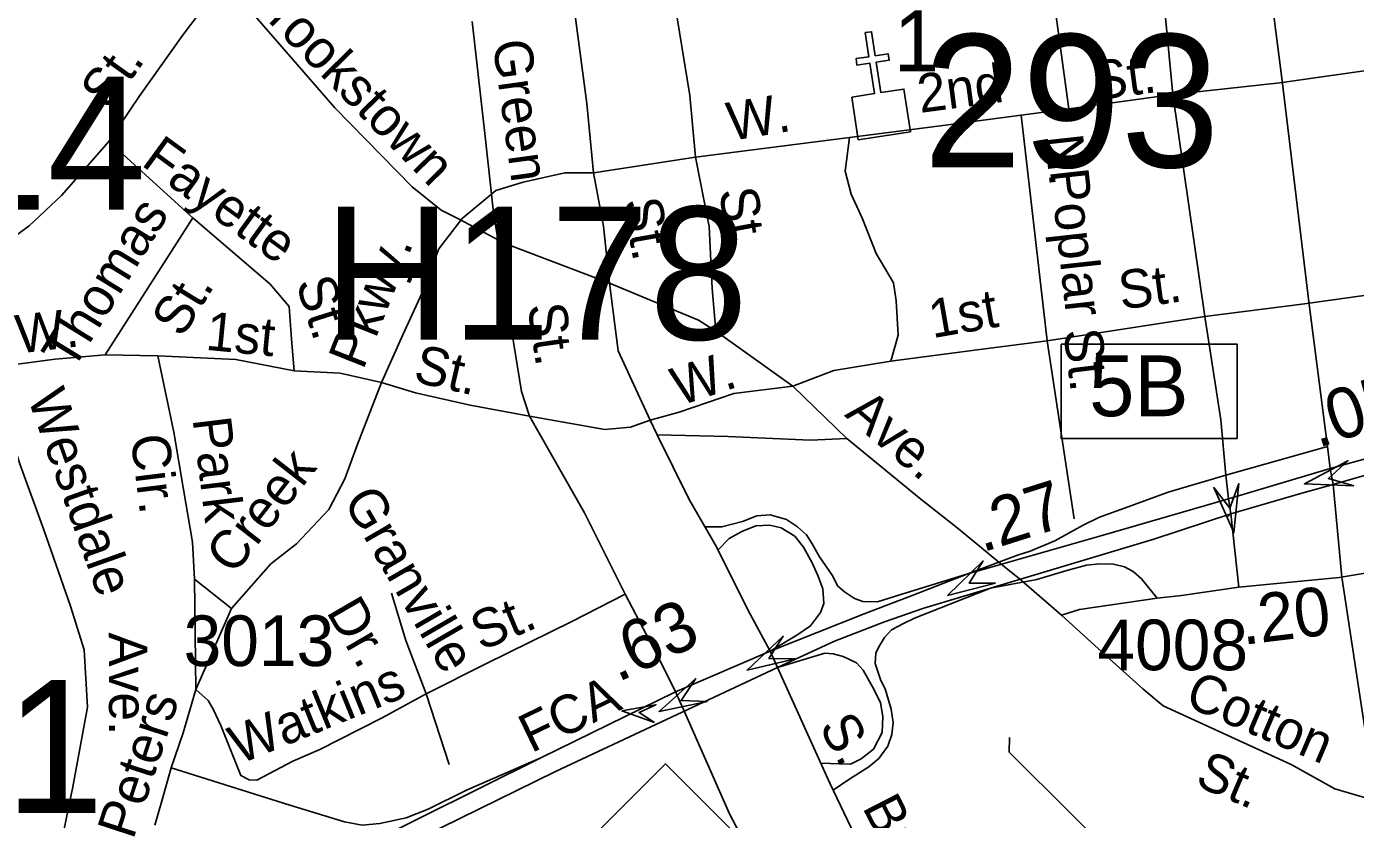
# Model space of a CAD drawing. Extents: x 1547597 to 1699558, y 810033 to 920809.
# Drawn here: x 1628319 to 1631601, y 854278 to 856236 of the extents above; entities that cross this region are included whole.
import ezdxf

# ---------------------------------------------------------------- set-up
doc = ezdxf.new("R2010")
doc.units = 0
for name, color, linetype in [('Exist Cultural Church CELL', 7, 'Continuous'), ('Exist Cultural Church Label', 7, 'Continuous'), ('Exist Hydrographic Creek Single Shore', 7, 'Continuous'), ('Exist Road Non-System Structure Non-Sys Other Number Label', 7, 'Continuous'), ('Exist Road Non-System Type 51', 7, 'Continuous'), ('Exist Road Non-System Type 51 Label', 7, 'Continuous'), ('Exist Road Primary Interstate Divided Center Attributed', 7, 'Continuous'), ('Exist Road Primary Interstate Interchange CELL', 7, 'Continuous'), ('Exist Road Primary Interstate Label', 7, 'Continuous'), ('Exist Road Primary Interstate Mileage Hundredths English Label', 7, 'Continuous'), ('Exist Road Primary Interstate Ramp 1 Lane Attributed', 7, 'Continuous'), ('Exist Road Primary Interstate Structure Cantilever Sign Number Label', 7, 'Continuous'), ('Exist Road Primary Interstate Structure Ovrhead Sign Attributed CELL', 7, 'Continuous'), ('Exist Road Primary NC Shield CELL', 7, 'Continuous'), ('Exist Road Primary US Structure Non-Sys NCDOT Attributed CELL', 7, 'Continuous'), ('Exist Road Primary US Structure Non-Sys NCDOT Number Label', 7, 'Continuous'), ('Exist Road Secondary Mileage Hundredths English Label', 7, 'Continuous'), ('Exist Road Secondary Structure Standard Bridge Attributed CELL', 7, 'Continuous'), ('Exist Road Secondary Structure Standard Bridge Number Label', 7, 'Continuous'), ('Exist Road Secondary Type 51 Attributed', 7, 'Continuous'), ('Exist Road Secondary Type 51 Divided Attributed', 7, 'Continuous'), ('Exist Road Secondary Type 51 Number Label', 7, 'Continuous')]:
    doc.layers.add(name, color=color, linetype=linetype)

msp = doc.modelspace()

# ---------------------------------------------------------------- linework, layer by layer
at = {"layer": 'Exist Cultural Church CELL'}
msp.add_lwpolyline([(1630356.6, 856061.6), (1630412.8, 856070.3), (1630401.4, 856145.6), (1630369.7, 856140.8), (1630367.3, 856156.6), (1630399, 856161.4), (1630389.9, 856220.8), (1630405.8, 856223.2), (1630414.8, 856163.8), (1630446.5, 856168.6), (1630448.9, 856152.8), (1630417.2, 856148), (1630428.7, 856072.7), (1630485.7, 856081.3), (1630501.7, 855976), (1630372.6, 855956.4)], close=True, dxfattribs=at)
at = {"layer": 'Exist Hydrographic Creek Single Shore'}
msp.add_line((1630745.6, 854444.2), (1630746.1, 854480.4), dxfattribs=at)
msp.add_lwpolyline([(1632644.9, 851920.7), (1632522.9, 852205.5), (1632509.9, 852481.5), (1632452.9, 852597.5), (1632189.9, 852901.6), (1632042.9, 853163.9), (1631910.8, 853265.1), (1631752.8, 853324.1), (1631670.9, 853434.1), (1631446.9, 853576.5), (1631210.9, 853981.8), (1630745.6, 854444.2)], dxfattribs=at)
at = {"layer": 'Exist Road Non-System Type 51'}
for p, q in [((1631111.3, 856464), (1631149.8, 856068.4)), ((1630839.2, 856425.4), (1630893.1, 856032.4)), ((1631668.4, 856132.7), (1631414.2, 856096.6)), ((1631414.2, 856096.6), (1631149.8, 856068.4)), ((1631149.8, 856068.4), (1630893.1, 856032.4)), ((1631149.8, 856068.4), (1631228.8, 855520.2)), ((1630893.1, 856032.4), (1630775, 856017)), ((1630775, 856017), (1630839.3, 855459.8)), ((1629970.5, 855913.2), (1629718.7, 855874.4)), ((1629478.1, 855831.3), (1629395, 855762)), ((1629472.4, 855776.5), (1629487, 855684.3)), ((1631474.9, 855551.3), (1631730.4, 855587.4)), ((1631228.8, 855520.2), (1631474.9, 855551.3)), ((1630839.3, 855459.8), (1631228.8, 855520.2)), ((1630839.3, 855459.8), (1630905.8, 855020.7)), ((1628643.4, 855422.8), (1628513.3, 855425.5)), ((1630344.3, 855219), (1630211.1, 855347.6)), ((1629876.1, 855227.4), (1629859.3, 855264)), ((1631280.6, 855128.5), (1631287.6, 855069.8)), ((1631545.5, 855105), (1631567.5, 854876.1)), ((1631293.2, 855032.5), (1631312.6, 854851.6)), ((1631567.5, 854876.1), (1631651.4, 854323.9)), ((1629305.3, 854587.9), (1629362.3, 854414.1)), ((1630302.6, 854367.5), (1630419.6, 854124.5))]:
    msp.add_line(p, q, dxfattribs=at)
for points in [[(1628806.7, 856350.6), (1628704.3, 856213.6), (1628598.2, 856065.3), (1628521.6, 855951.8)], [(1628806.7, 856350.6), (1629079.8, 856035.5), (1629270.8, 855839.9), (1629343, 855782.8), (1629387.4, 855760.6)], [(1629917.9, 856303.7), (1629956.7, 856065.5), (1629970.5, 855913.2)], [(1629718.7, 855874.4), (1629702.1, 856046.2), (1629671.6, 856281.6)], [(1629419.7, 856248.3), (1629450.6, 855972), (1629472.4, 855776.5)], [(1630775, 856017), (1630569.1, 855990.3), (1630350.9, 855962)], [(1628521.6, 855951.8), (1628405.4, 855818.8), (1628325.1, 855744.1), (1628133.7, 855604.1)], [(1628521.6, 855951.8), (1628729.2, 855763.5)], [(1630350.9, 855962), (1630144.9, 855935.4), (1629970.5, 855913.2)], [(1630350.9, 855962), (1630340.4, 855878.7), (1630355.3, 855821.8), (1630382.9, 855760.9), (1630417.1, 855675.7), (1630460, 855603.1), (1630466.4, 855558.7), (1630471.5, 855473.9), (1630453.5, 855409.7)], [(1630020.9, 855484), (1630012, 855589.1), (1630004.6, 855741.9), (1629970.5, 855913.2)], [(1629718.7, 855874.4), (1629648.4, 855874.9), (1629545, 855851.4), (1629478.1, 855831.3)], [(1629758.5, 855602.5), (1629743.8, 855742.7), (1629718.7, 855874.4)], [(1628729.2, 855763.5), (1628513.3, 855425.5)], [(1628729.2, 855763.5), (1628920.2, 855600), (1628967.3, 855544.6), (1628972.8, 855464.3), (1628979.9, 855385.4)], [(1629395, 855762), (1629336.9, 855687.3), (1629295.1, 855576.3), (1629247.8, 855474.6), (1629195.3, 855357.1)], [(1629387.4, 855760.6), (1629498.5, 855701.3)], [(1629498.5, 855701.3), (1629758.5, 855602.5)], [(1629487, 855684.3), (1629500.7, 855583.6), (1629541.3, 855334.4), (1629561, 855274.2)], [(1629859.3, 855264), (1629818.8, 855350.8), (1629779.8, 855435.2), (1629758.5, 855602.5)], [(1629758.5, 855602.5), (1629977.9, 855510.7), (1630020.9, 855484)], [(1631228.8, 855520.2), (1631268.6, 855265.1), (1631280.6, 855128.5)], [(1630020.9, 855484), (1630211.1, 855347.6)], [(1630839.3, 855459.8), (1630666.6, 855438), (1630453.5, 855409.7)], [(1628513.3, 855425.5), (1628389.4, 855414.2), (1628214.8, 855391.9)], [(1628979.9, 855385.4), (1628836, 855414.1), (1628643.4, 855422.8)], [(1628643.4, 855422.8), (1628682.2, 855234.4), (1628706.2, 855092.8), (1628728.3, 854962.6), (1628733.9, 854871.2)], [(1630453.5, 855409.7), (1630312.4, 855386.6), (1630211.1, 855347.6)], [(1628214.8, 855391.9), (1628258.9, 855292), (1628303.2, 855153.5), (1628361.3, 854992.9), (1628427.7, 854804.5), (1628460.9, 854696.5), (1628469.2, 854555.3), (1628433.3, 854358.6), (1628411.1, 854250.6), (1628419.4, 854142.6)], [(1629195.3, 855357.1), (1629093.3, 855379.7), (1628979.9, 855385.4)], [(1629195.3, 855357.1), (1629134.9, 855202.5), (1629104.6, 855119), (1629065.5, 855043.6), (1628985.4, 854958.8), (1628921.8, 854908.9), (1628825.2, 854799.2)], [(1629561, 855274.2), (1629414.1, 855300.8), (1629279.4, 855331.5), (1629195.3, 855357.1)], [(1629859.3, 855264), (1629930.2, 855283.6), (1630065.5, 855329.4), (1630211.1, 855347.6)], [(1629561, 855274.2), (1629696.5, 855035.1), (1629797.1, 854834.5)], [(1629859.3, 855264), (1629810.2, 855246.4), (1629746.6, 855241.3), (1629561, 855274.2)], [(1629876.1, 855227.4), (1629955.2, 855068.3), (1630022.9, 854951.5)], [(1630344.3, 855219), (1630254.9, 855214.9), (1630050.9, 855223.2), (1629876.1, 855227.4)], [(1630734.2, 854901.6), (1630620.5, 854995.4), (1630523.2, 855072), (1630344.3, 855219)], [(1631287.6, 855069.8), (1631293.2, 855032.5), (1631286, 855025.7)], [(1630022.9, 854951.5), (1630099.5, 854797.3), (1630155.4, 854693.7)], [(1630770.4, 854872.9), (1630750.1, 854888.3), (1630734.2, 854901.6)], [(1628733.9, 854871.2), (1628825.2, 854799.2)], [(1628733.9, 854871.2), (1628736.7, 854599.2)], [(1630770.4, 854872.9), (1630875.1, 854782.2), (1630993.1, 854674.4), (1631076, 854600.3)], [(1629305.3, 854587.9), (1629255.7, 854719.9), (1629219.7, 854836.9)], [(1629797.1, 854834.5), (1629665.6, 854766.9), (1629454.8, 854663.5), (1629305.3, 854587.9)], [(1629797.1, 854834.5), (1629885.1, 854666.4), (1629923.7, 854588.1)], [(1628825.2, 854799.2), (1628736.7, 854599.2)], [(1630155.4, 854693.7), (1630173.5, 854653.6), (1630302.6, 854367.5)], [(1628736.7, 854599.2), (1628705.6, 854491.5), (1628676.1, 854405.5)], [(1629305.3, 854587.9), (1629195.8, 854528.4), (1629043.5, 854450.4), (1628976.1, 854421.9), (1628887.9, 854375.2), (1628868.7, 854376.2), (1628847.9, 854386.3), (1628798.3, 854509.6), (1628779.4, 854550.7), (1628767.6, 854571.5), (1628736.7, 854599.2)], [(1630200.4, 854009.6), (1630131.7, 854146.1), (1630055, 854292), (1629941, 854549.6), (1629932.2, 854569.3), (1629923.7, 854588.1)], [(1631076, 854600.3), (1631126.2, 854558.7), (1631441.8, 854413.5), (1631549.8, 854353.3), (1631651.4, 854323.9)]]:
    msp.add_lwpolyline(points, dxfattribs=at)
at = {"layer": 'Exist Road Primary Interstate Divided Center Attributed'}
for points in [[(1631790.2, 855221.9), (1631645.8, 855174.4), (1631538.6, 855145)], [(1631545.5, 855105), (1631642.6, 855132.8), (1631796.6, 855182.4)], [(1631538.6, 855145), (1631287.6, 855069.8)], [(1631293.2, 855032.5), (1631468.2, 855083.7), (1631545.5, 855105)], [(1631287.6, 855069.8), (1630971.8, 854978), (1630643.8, 854884.1)], [(1630699.1, 854849.5), (1631103.1, 854969.9), (1631293.2, 855032.5)], [(1630643.8, 854884.1), (1630506.2, 854830.8), (1630387.7, 854786), (1630155.4, 854693.7), (1629920.1, 854592.3), (1629590.8, 854431.1), (1629137.3, 854205.2), (1628897.5, 854085.8), (1628714.3, 853997.4)], [(1628918.2, 854048.9), (1629625, 854396.4), (1630173.5, 854653.6), (1630314.1, 854718.2), (1630437.4, 854766.2), (1630534.7, 854799.8), (1630699.1, 854849.5)]]:
    msp.add_lwpolyline(points, dxfattribs=at)
at = {"layer": 'Exist Road Primary Interstate Interchange CELL'}
msp.add_lwpolyline([(1630873.6, 855452), (1631308.5, 855452), (1631308.5, 855218.8), (1630873.6, 855218.8)], close=True, dxfattribs=at)
at = {"layer": 'Exist Road Primary Interstate Ramp 1 Lane Attributed'}
for points in [[(1631531.4, 855198.9), (1631280.6, 855128.5), (1631138.5, 855086), (1631030.2, 855046.7), (1630968.5, 855024.2), (1630928.4, 855004.9), (1630858.3, 854965.6), (1630797.5, 854940.2), (1630766.2, 854930.3), (1630643.8, 854884.1)], [(1630643.8, 854884.1), (1630478, 854833.3), (1630420.1, 854815.7), (1630384.5, 854816.4), (1630363.7, 854823.8), (1630338.7, 854839.8), (1630322.7, 854854.3), (1630308.2, 854880.9), (1630276.9, 854926.6), (1630258.7, 854958.9), (1630244.7, 854980.5), (1630223.1, 855000.4), (1630195.8, 855018.6), (1630155.3, 855030.2), (1630122.2, 855027.7), (1630086.6, 855013.6), (1630036.1, 855000.4), (1629994.7, 855000.4)], [(1630027, 854944), (1630054.3, 854971.4), (1630084.9, 854988.8), (1630119.7, 855002.8), (1630154.5, 855004.5), (1630182.6, 854997.9), (1630216.5, 854977.2), (1630238, 854950.7), (1630258.7, 854911.7), (1630272.8, 854880.3), (1630285.2, 854847.1), (1630287.4, 854811), (1630279.4, 854789.2), (1630254.6, 854756), (1630221, 854733.1), (1630155.4, 854693.7)], [(1630699.1, 854849.5), (1630814, 854870.5), (1630888, 854892.7), (1630936.1, 854906.3), (1630969.3, 854909.4), (1631003.3, 854908.1), (1631030.5, 854901.8), (1631051.4, 854890), (1631072.3, 854871.8), (1631110.7, 854824.4)], [(1630310.6, 854350.2), (1630349.3, 854376.9), (1630399.2, 854407.8), (1630423.7, 854428.7), (1630445.5, 854458.7), (1630455.5, 854487.8), (1630459.1, 854517.8), (1630453.7, 854550.5), (1630439.2, 854600.5), (1630428.3, 854621.4), (1630414.8, 854662.9), (1630416.2, 854688.4), (1630423.9, 854704.6), (1630437.6, 854727.3), (1630455, 854746.4), (1630484.8, 854761.8), (1630512.1, 854775.2), (1630699.1, 854849.5)], [(1630173.5, 854653.6), (1630290.2, 854688.7), (1630311.1, 854686.8), (1630335.6, 854680.5), (1630368.3, 854665), (1630384.7, 854646.9), (1630408.3, 854605.1), (1630427.4, 854566.9), (1630433.7, 854531.4), (1630431.9, 854492.4), (1630410.1, 854451.5), (1630380.1, 854427.8), (1630353.8, 854414.2), (1630279.6, 854417)], [(1628676.1, 854405.5), (1628851.1, 854350.1), (1628969.1, 854313.2), (1629104.2, 854271.9), (1629147.8, 854264.2), (1629191.5, 854268.4), (1629256.1, 854281.8), (1629310.5, 854303.6), (1629405.6, 854350.2), (1629590.8, 854431.1)]]:
    msp.add_lwpolyline(points, dxfattribs=at)
at = {"layer": 'Exist Road Primary Interstate Structure Ovrhead Sign Attributed CELL'}
msp.add_lwpolyline([(1629869.3, 854517.1), (1629789, 854546.2), (1629873, 854561.2), (1629831.5, 854542.5)], close=True, dxfattribs=at)
at = {"layer": 'Exist Road Primary NC Shield CELL'}
msp.add_lwpolyline([(1629563.9, 854082.1), (1629896.9, 854415.1), (1630229.9, 854082.1), (1629896.9, 853749.1)], close=True, dxfattribs=at)
at = {"layer": 'Exist Road Primary US Structure Non-Sys NCDOT Attributed CELL'}
for points in [[(1631312.9, 855107.5), (1631300.7, 854986.2), (1631250.6, 855097.4), (1631290.9, 855046.4)], [(1630217.2, 854674.6), (1630098.4, 854647), (1630187.5, 854730.3), (1630152.2, 854675.7)], [(1630000.1, 854569.4), (1629880.8, 854544.5), (1629971.6, 854625.8), (1629935.2, 854572)]]:
    msp.add_lwpolyline(points, close=True, dxfattribs=at)
at = {"layer": 'Exist Road Secondary Structure Standard Bridge Attributed CELL'}
for points in [[(1631596.5, 855102.2), (1631474.7, 855106.6), (1631582.3, 855163.7), (1631534.1, 855120.2)], [(1630711.7, 854861.3), (1630593.5, 854831.4), (1630681, 854916.4), (1630646.8, 854861.1)]]:
    msp.add_lwpolyline(points, close=True, dxfattribs=at)
at = {"layer": 'Exist Road Secondary Type 51 Attributed'}
for points in [[(1630478.9, 860098.3), (1630547.1, 860009.3), (1630601.9, 859931.1), (1630644.5, 859853.9), (1630689.6, 859770.3), (1630711.9, 859728.5), (1630734.9, 859679.6), (1630760.9, 859603.3), (1630805.5, 859473.8), (1630821.3, 859420.1), (1630862.8, 859228.9), (1630920.4, 858943.8), (1630991, 858586.5), (1631024.1, 858425.7), (1631113.7, 857997.3), (1631202, 857722.5), (1631224.2, 857603), (1631237.8, 857539.5), (1631247.8, 857461.3), (1631317.3, 856897.8), (1631419.7, 856101.5), (1631485.2, 855556.3), (1631531.4, 855198.9)], [(1631531.4, 855198.9), (1631538.6, 855145)], [(1631538.6, 855145), (1631545.5, 855105)], [(1630875.1, 854782.2), (1630919.4, 854796.6), (1631110.7, 854824.4), (1631171, 854831.3), (1631312.6, 854851.6), (1631560.2, 854875.2), (1631831.2, 854920.4)]]:
    msp.add_lwpolyline(points, dxfattribs=at)
at = {"layer": 'Exist Road Secondary Type 51 Divided Attributed'}
msp.add_lwpolyline([(1628635.3, 854263.8), (1628653.4, 854326.8), (1628676.1, 854405.5)], dxfattribs=at)

# ---------------------------------------------------------------- texts
at = {"layer": 'Exist Cultural Church Label'}
msp.add_text('1', height=150, dxfattribs=at).set_placement((1630461, 856125.6))
at = {"layer": 'Exist Road Non-System Structure Non-Sys Other Number Label'}
msp.add_text('J381', height=328.08, dxfattribs=at).set_placement((1627558.7, 854293.9))
at = {"layer": 'Exist Road Non-System Type 51 Label'}
for s, rotation, p in [('Brookstown', 314.3455, (1628853.2, 856310.9)), ('Green', 277.7454, (1629469.5, 856198.1)), ('St.', 54.4332, (1628522.7, 856026.7)), ('2nd', 7.5891, (1630525.6, 856022.5)), ('St.', 7.4271, (1630958.8, 856054.2)), ('W.', 9.3723, (1630057.1, 855953.2)), ('Fayette', 323.9544, (1628599.2, 855895.1)), ('N.', 276.3247, (1630832.7, 855965.2)), ('Poplar', 276.3247, (1630846.1, 855881.1)), ('St.', 280.6701, (1630027.6, 855830.3)), ('Thomas', 58.4644, (1628432.5, 855383)), ('St.', 279.8556, (1629791.5, 855806)), ('Pkwy.', 68.3972, (1629150.1, 855385.7)), ('St.', 7.605, (1631022.1, 855536.9)), ('St.', 58.4644, (1628703.2, 855464.5)), ('St.', 287.6525, (1628983.2, 855603.5)), ('1st', 9.919, (1630556.2, 855466.1)), ('St.', 278.2108, (1629555.7, 855547.4)), ('W.', 6.825, (1628297.7, 855428.1)), ('1st', 354.4216, (1628758.9, 855438)), ('St.', 276.9276, (1630879.4, 855485)), ('St.', 347.1367, (1629271, 855359.4)), ('W.', 18.2747, (1629931, 855298.3)), ('Westdale', 289.5231, (1628320.3, 855320.8)), ('Ave.', 319.6591, (1630336.8, 855275.1)), ('Park', 276.9439, (1628728.5, 855267.1)), ('Cir.', 277.0524, (1628575.4, 855224.3)), ('Creek', 52.0739, (1628829.9, 854878.6)), ('Granville', 300.1114, (1629099.1, 855065.3)), ('Dr.', 300.1114, (1629057.6, 854791.1)), ('St.', 22.7091, (1629441.2, 854693.5)), ('Ave.', 270.186, (1628521.8, 854739.9)), ('Watkins', 22.2064, (1628843.9, 854413.1)), ('Cotton', 336.8873, (1631175.3, 854560.6)), ('Peters', 71.8878, (1628582, 854226)), ('S.', 298.8589, (1630274.4, 854507.6)), ('St.', 336.8873, (1631201.4, 854363.4)), ('Broad', 297.2142, (1630381.8, 854308.4))]:
    msp.add_text(s, height=95, rotation=rotation, dxfattribs=at).set_placement(p)
at = {"layer": 'Exist Road Primary Interstate Interchange CELL'}
msp.add_text('5B', height=150, dxfattribs=at).set_placement((1630943.1, 855273.7))
at = {"layer": 'Exist Road Primary Interstate Label'}
msp.add_text('FCA', height=95, rotation=25.8342, dxfattribs=at).set_placement((1629565.1, 854441.1))
at = {"layer": 'Exist Road Primary Interstate Mileage Hundredths English Label'}
for s, rotation, p in [('.05', 18.2123, (1631507.2, 855194.5)), ('.63', 25.1272, (1629778.5, 854615.7))]:
    msp.add_text(s, height=125, rotation=rotation, dxfattribs=at).set_placement(p)
at = {"layer": 'Exist Road Primary Interstate Structure Cantilever Sign Number Label'}
msp.add_text('L614', height=328.08, dxfattribs=at).set_placement((1627638.2, 855784.1))
at = {"layer": 'Exist Road Primary US Structure Non-Sys NCDOT Number Label'}
msp.add_text('H178', height=328.08, dxfattribs=at).set_placement((1629051.6, 855462.9))
at = {"layer": 'Exist Road Secondary Mileage Hundredths English Label'}
for s, rotation, p in [('.27', 17.5375, (1630678.9, 854937)), ('.20', 6.9016, (1631323, 854709))]:
    msp.add_text(s, height=120, rotation=rotation, dxfattribs=at).set_placement(p)
at = {"layer": 'Exist Road Secondary Structure Standard Bridge Number Label'}
msp.add_text('293', height=328.08, dxfattribs=at).set_placement((1630533.3, 855888.5))
at = {"layer": 'Exist Road Secondary Type 51 Number Label'}
for s, p in [('3013', (1628706.7, 854656.8)), ('4008', (1630963.6, 854646.5))]:
    msp.add_text(s, height=125, dxfattribs=at).set_placement(p)

doc.saveas('drawing.dxf')
